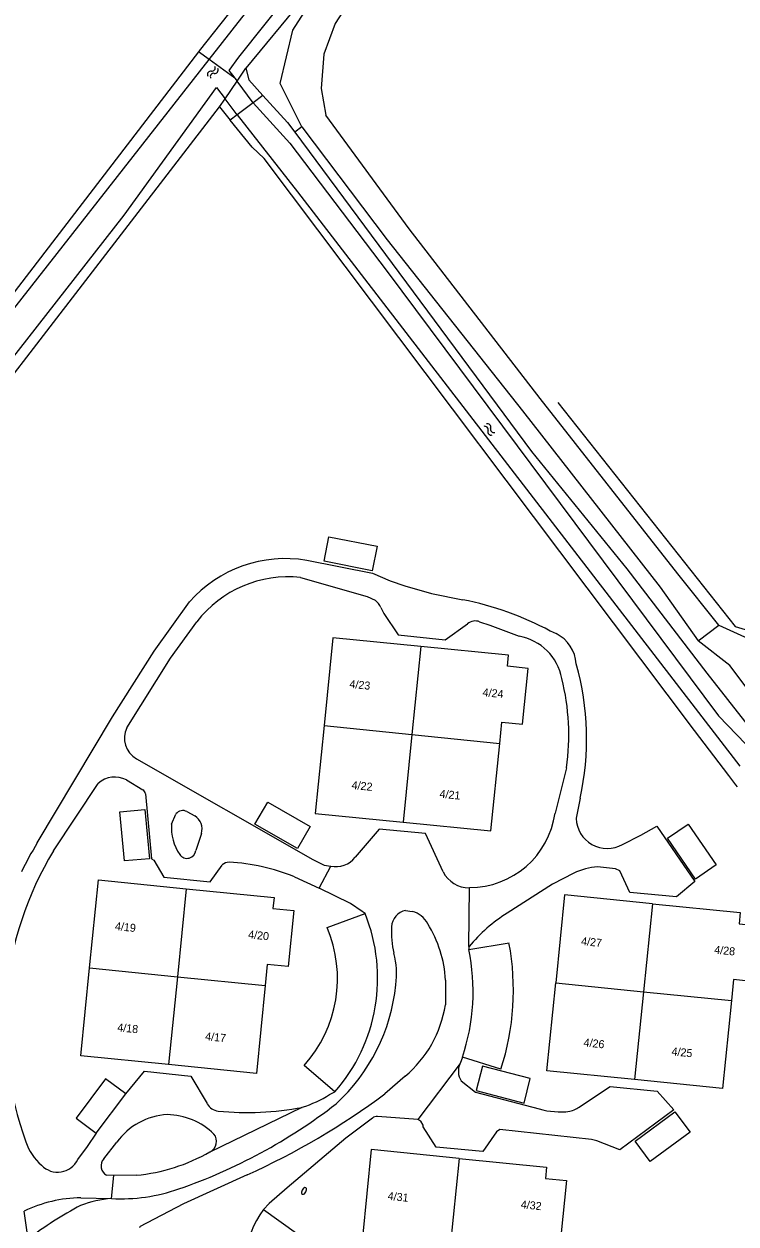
# Model space of a CAD drawing. Extents: x 136000 to 141014, y 402000 to 403500.
# Drawn here: x 137734.8 to 137823.8, y 402938.4 to 403088.3 of the extents above; entities that cross this region are included whole.
import ezdxf

# ---------------------------------------------------------------- set-up
doc = ezdxf.new("R2010")
doc.units = 0
for name, color, linetype in [('gg-afsc-hekwerk', 7, 'Continuous'), ('gg-anno-huisnummerreeks BGT', 7, 'Continuous'), ('gg-bbg-gedigitaliseerde bijgebouw', 7, 'Continuous'), ('gg-bbg-hoofdgebouw', 7, 'Continuous'), ('gg-bbg-tussenscheiding', 7, 'Continuous'), ('gg-knt-onverhard', 7, 'Continuous'), ('gg-knt-verharding', 7, 'Continuous'), ('gg-knt-verharding nz', 7, 'Continuous'), ('gg-kntw-bovenkant insteek waterloop', 7, 'Continuous'), ('gg-kntw-waterlijn', 7, 'Continuous'), ('gg-kwrk-lijn stuw', 7, 'Continuous'), ('gt-grn-groengrens', 7, 'Continuous'), ('gt-grn-vlakafsluiter', 7, 'Continuous'), ('gt-symb-brandkraan', 7, 'Continuous'), ('gt-symb-watersymbool', 7, 'Continuous')]:
    doc.layers.add(name, color=color, linetype=linetype)

# ---------------------------------------------------------------- blocks, each defined once
blk = doc.blocks.new('gt0-WA')
at = {"layer": 'gt-symb-watersymbool'}
for centre, start, end in [((-0.32, 0.02), 28.0725, 151.9275), ((0.43, 0.42), 208.0725, 331.9275), ((-0.32, -0.43), 28.0725, 151.9275), ((0.43, -0.03), 208.0725, 331.9275)]:
    blk.add_arc(centre, 0.425, start, end, dxfattribs=at)
blk = doc.blocks.new('gt0-BR')
at = {"layer": 'gt-symb-brandkraan'}
for centre, radius, start, end in [((-0.24, 0), 0.206, 107.5669, 252.4331), ((0.6, -2.66), 3, 106.892, 107.5669), ((0, -0.69), 0.938, 73.108, 106.892), ((-0.6, -2.66), 3, 72.4331, 73.108), ((0.24, 0), 0.206, 287.567, 72.4331), ((0.6, 2.66), 3, 252.4331, 253.108), ((0, 0.69), 0.938, 253.108, 286.8921), ((-0.6, 2.66), 3, 286.8921, 287.567)]:
    blk.add_arc(centre, radius, start, end, dxfattribs=at)

msp = doc.modelspace()

# ---------------------------------------------------------------- linework, layer by layer
at = {"layer": 'gg-afsc-hekwerk'}
msp.add_lwpolyline([(137801.52, 403040.96), (137823.69, 403012.99), (137826.49, 403012.14), (137826.96, 403011.96)], dxfattribs=at)
at = {"layer": 'gg-bbg-gedigitaliseerde bijgebouw'}
for p, q in [((137743.85, 402949.69), (137747.54, 402954.62)), ((137741.33, 402951.57), (137743.85, 402949.69))]:
    msp.add_line(p, q, dxfattribs=at)
for points in [[(137772.32, 403021.14), (137772.93, 403024.2), (137778.93, 403023.01), (137778.33, 403019.94), (137772.32, 403021.14)], [(137763.68, 402988.32), (137765.3, 402991.03), (137770.57, 402988), (137769.01, 402985.27), (137763.68, 402988.32)], [(137746.79, 402989.83), (137749.93, 402990.12), (137750.5, 402983.99), (137747.36, 402983.7), (137746.79, 402989.83)], [(137815.25, 402986.54), (137817.83, 402988.31), (137821.33, 402983.21), (137818.75, 402981.44), (137815.25, 402986.54)], [(137797.31, 402953.46), (137798.08, 402956.53), (137792.12, 402958.09), (137791.34, 402955.05), (137797.31, 402953.46)], [(137747.54, 402954.62), (137745.02, 402956.51), (137741.33, 402951.57)], [(137813.07, 402946.18), (137811.21, 402948.71), (137816.15, 402952.37), (137818.06, 402949.84), (137813.07, 402946.18)]]:
    msp.add_lwpolyline(points, dxfattribs=at)
at = {"layer": 'gg-bbg-hoofdgebouw'}
for points in [[(137784.4, 403010.49), (137773.43, 403011.58), (137772.31, 403000.61)], [(137794.26, 402998.39), (137794.53, 403001.04), (137797.12, 403000.78), (137797.82, 403007.76), (137795.23, 403008.02), (137795.36, 403009.41), (137784.4, 403010.49)], [(137772.31, 403000.61), (137771.19, 402989.64), (137782.18, 402988.55)], [(137782.18, 402988.55), (137793.17, 402987.46), (137794.26, 402998.39)], [(137743.02, 402970.36), (137744.13, 402981.33), (137755.1, 402980.24)], [(137755.1, 402980.24), (137766.07, 402979.15), (137765.93, 402977.76), (137768.53, 402977.5), (137767.82, 402970.52), (137765.22, 402970.78), (137764.96, 402968.14)], [(137813.34, 402978.35), (137802.37, 402979.46), (137801.27, 402968.48)], [(137813.34, 402978.35), (137824.31, 402977.25), (137824.17, 402975.86), (137826.77, 402975.61), (137826.07, 402968.62), (137823.47, 402968.88), (137823.21, 402966.26)], [(137752.88, 402958.27), (137741.91, 402959.38), (137743.02, 402970.36)], [(137764.96, 402968.14), (137763.85, 402957.16), (137752.88, 402958.27)], [(137811.12, 402956.39), (137800.16, 402957.49), (137801.27, 402968.48)], [(137823.21, 402966.26), (137822.11, 402955.28), (137811.12, 402956.39)], [(137789.18, 402946.55), (137778.22, 402947.65), (137777.1, 402936.66)], [(137789.18, 402946.55), (137800.13, 402945.44), (137800, 402944.05), (137802.59, 402943.8), (137801.9, 402936.82), (137799.31, 402937.07), (137799.05, 402934.44)]]:
    msp.add_lwpolyline(points, dxfattribs=at)
at = {"layer": 'gg-bbg-tussenscheiding'}
for p, q in [((137784.4, 403010.49), (137783.28, 402999.5)), ((137772.31, 403000.61), (137783.28, 402999.5)), ((137783.28, 402999.5), (137782.18, 402988.55)), ((137783.28, 402999.5), (137794.26, 402998.39)), ((137755.1, 402980.24), (137753.99, 402969.25)), ((137813.34, 402978.35), (137812.23, 402967.37)), ((137743.02, 402970.36), (137753.99, 402969.25)), ((137753.99, 402969.25), (137752.88, 402958.27)), ((137753.99, 402969.25), (137764.96, 402968.14)), ((137801.27, 402968.48), (137812.23, 402967.37)), ((137812.23, 402967.37), (137811.12, 402956.39)), ((137812.23, 402967.37), (137823.21, 402966.26)), ((137789.18, 402946.55), (137788.07, 402935.55))]:
    msp.add_line(p, q, dxfattribs=at)
at = {"layer": 'gg-knt-onverhard'}
for points in [[(137769.55, 403075.4), (137766.81, 403080.81), (137768.42, 403087.5), (137774.63, 403097.17), (137871.84, 403222.79)], [(137878.86, 403220.54), (137874.39, 403219.53), (137869.43, 403214.21), (137825.7, 403158.07), (137779.86, 403097.85), (137773.69, 403088.3), (137772.27, 403084.47), (137771.97, 403080.2), (137772.54, 403076.85)], [(137821.63, 403013.16), (137816.54, 403019.57), (137799.31, 403041.48), (137782.95, 403062.65), (137772.54, 403076.85)], [(137769.55, 403075.4), (137780.2, 403061.27), (137797.11, 403039.92), (137814.32, 403017.9), (137819.08, 403011.19)]]:
    msp.add_lwpolyline(points, dxfattribs=at)
at = {"layer": 'gg-knt-verharding'}
for p, q in [((137819.08, 403011.19), (137821.63, 403013.16)), ((137800.58, 403012.43), (137801.32, 403012.1)), ((137802.6, 402995.34), (137801.19, 402989.69)), ((137747.62, 402993.84), (137749.67, 402992.58)), ((137738.5, 402984.95), (137744.09, 402993.39)), ((137804.31, 402991.54), (137803.81, 402989.03)), ((137753.24, 402988.32), (137753.8, 402989.57)), ((137755.18, 402989.87), (137756.18, 402989.34)), ((137756.99, 402987.15), (137756.27, 402985.03)), ((137768.61, 402981.74), (137771.72, 402980.29)), ((137772.7, 402975.39), (137777.45, 402977.13)), ((137782.51, 402977.52), (137783.34, 402977.4)), ((137790.4, 402972.66), (137795.43, 402973.46)), ((137790.42, 402973.02), (137790.4, 402972.66)), ((137787.49, 402968.82), (137787.47, 402965.72)), ((137789.6, 402959.2), (137789.32, 402958.39)), ((137794.41, 402957.69), (137789.6, 402959.2)), ((137773.68, 402954.87), (137769.81, 402958.16)), ((137782.43, 402956.82), (137779.92, 402954.61)), ((137773.01, 402954.53), (137773.68, 402954.87)), ((137784.03, 402951.41), (137779.01, 402951.8)), ((137744.78, 402946.51), (137746.4, 402948.58)), ((137746.06, 402944.4), (137745.14, 402944.45)), ((137748.84, 402944.46), (137746.06, 402944.4)), ((137741.91, 402941.63), (137745.76, 402941.54)), ((137734.81, 402939.95), (137735.31, 402936.47)), ((137764.75, 402940.18), (137768.89, 402937.2))]:
    msp.add_line(p, q, dxfattribs=at)
for points in [[(137770.14, 403021.26), (137778.35, 403019.67), (137780.58, 403018.71), (137782.39, 403018.08), (137785.75, 403017.12), (137789.66, 403016.34)], [(137769.37, 403019.11), (137777.71, 403016.75), (137778.71, 403016.28)], [(137736.47, 402985.96), (137745.88, 403001.7), (137751.07, 403009.92), (137755.48, 403016.08)], [(137779.4, 403015.37), (137779.77, 403014.63), (137781.57, 403011.94), (137787.43, 403011.34), (137790.25, 403013.32)], [(137747.66, 403000.32), (137753.13, 403009.04), (137756.41, 403013.58)], [(137791.75, 403013.58), (137793.01, 403013.15), (137796.68, 403011.78)], [(137821.63, 403013.16), (137825.3, 403011.49), (137826.13, 403010.6)], [(137894.08, 402913.47), (137823.01, 403008.12), (137819.08, 403011.19)], [(137748.87, 402996.47), (137770.9, 402983.87), (137772.33, 402983.2), (137773.14, 402983.07)], [(137749.98, 402992.1), (137750.75, 402983.99), (137751.05, 402983.8), (137752.29, 402981.67), (137758.09, 402981.08), (137759.6, 402983.2)], [(137787.18, 402982.34), (137784.99, 402987.12), (137779.18, 402987.67), (137776.2, 402984.19)], [(137809.61, 402985.75), (137811.9, 402986.91), (137813.88, 402988.07), (137818.64, 402981.12), (137816.35, 402979.21), (137810.53, 402979.78), (137809.29, 402982.48), (137808.72, 402982.74), (137806.5, 402982.96)], [(137803.52, 402982.19), (137800.85, 402980.8), (137795.2, 402977.2)], [(137777.45, 402977.13), (137777.06, 402977.39), (137775.62, 402978.4), (137771.72, 402980.29)], [(137747.54, 402954.62), (137749.86, 402957.43), (137755.68, 402956.84), (137757.69, 402953.39)], [(137789.44, 402956.25), (137791.25, 402954.81), (137799.2, 402952.74)], [(137804.36, 402953.08), (137808.07, 402955.52), (137813.94, 402954.96), (137816.04, 402952.6), (137809.27, 402947.62), (137806.4, 402948.73), (137805.75, 402948.92), (137794.28, 402950.16), (137793.86, 402949.87), (137792.17, 402947.4), (137786.34, 402947.95), (137784.68, 402950.49), (137784.7, 402950.69), (137784.41, 402951.19), (137784.03, 402951.41)], [(137778.37, 402951.59), (137775.04, 402949.08), (137767.7, 402942.88), (137765.44, 402940.91), (137764.75, 402940.18)], [(137743.85, 402949.69), (137742.73, 402948.02), (137741.52, 402946.41)], [(137762.7, 402944.49), (137754.73, 402940.86), (137749.25, 402938.02), (137749.3, 402937.91)]]:
    msp.add_lwpolyline(points, dxfattribs=at)
for centre, radius, start, end in [((137767.49, 403005.43), 16.04, 80.4864, 138.4464), ((137767.8, 403004.86), 14.34, 83.6962, 142.5493), ((137777.25, 403014.44), 2.34, 23.2533, 51.6041), ((137782.36, 402978.71), 38.32, 61.613, 79.0242), ((137791.23, 403012.17), 1.51, 69.6238, 130.2657), ((137795.57, 403005.31), 6.56, 10.2799, 80.2799), ((137799.3, 403008.03), 4.54, 3.6424, 63.6678), ((137771.01, 402999), 34.12, 347.3717, 15.851), ((137774.42, 402999.47), 28.48, 351.6761, 14.2555), ((137750.28, 402999.03), 2.91, 153.6829, 241.1913), ((137746.18, 402991.1), 3.09, 62.1575, 132.3959), ((137749.28, 402991.99), 0.717, 9.0986, 56.2879), ((137754.66, 402988.93), 1.07, 60.7123, 143.1821), ((137755.06, 402987.67), 2.01, 344.9578, 56.1198), ((137790.46, 402991.2), 10.83, 270.0897, 351.9846), ((137807.72, 402989.17), 3.91, 182.11, 298.9226), ((137759.41, 402987.94), 6.18, 176.5287, 213.8214), ((137774.2, 402963.25), 41.78, 148.7014, 200.4781), ((137774.66, 402962.79), 44.67, 148.7562, 154.0539), ((137755.18, 402985.13), 1.1, 214.7752, 354.8193), ((137760.45, 402982.31), 1.24, 89.9247, 133.8391), ((137759.08, 402958.05), 25.53, 68.0878, 86.9097), ((137773.81, 402985.97), 2.98, 257.0919, 323.1664), ((137790.45, 402984.06), 3.7, 207.8639, 270.3571), ((137806.95, 402975.08), 7.89, 93.2657, 115.7378), ((137757.45, 402969.07), 21.56, 318.8124, 21.9483), ((137782.96, 402975.35), 2.22, 101.7728, 176.3812), ((137782.55, 402974.43), 3.07, 27.8452, 75.1618), ((137806.93, 402958.98), 21.67, 122.7591, 139.6009), ((137772.46, 402967.95), 15.06, 3.3221, 31.7181), ((137757.73, 402969.04), 16.26, 317.9882, 22.9717), ((137792.4, 402974.79), 11.67, 176.5502, 192.937), ((137765.34, 402967.39), 25.6, 341.3321, 11.8761), ((137764.41, 402967.54), 31.57, 341.8172, 10.8035), ((137771.46, 402969.59), 9.91, 352.1758, 15.1453), ((137758.02, 402970.6), 23.38, 312.4842, 354.1917), ((137773.15, 402967.96), 14.5, 309.8266, 351.116), ((137791.19, 402957.42), 2.1, 152.7488, 213.8487), ((137723.5, 403030.82), 94.82, 294.4239, 306.5136), ((137764.77, 402967.74), 15.57, 288.0359, 301.9576), ((137731.79, 403007.55), 68.57, 289.0389, 307.7915), ((137759.27, 402954.25), 1.8, 208.8285, 264.0582), ((137802.18, 402955.91), 3.57, 283.6459, 307.5075), ((137753.18, 402943.66), 8.37, 93.2053, 144.0601), ((137752.57, 402943.42), 8.6, 45.9098, 89.0679), ((137762.69, 402989.3), 37.02, 264.4157, 280.7504), ((137778.95, 402950.86), 0.936, 86.5, 128.8149), ((137801.85, 402962.06), 9.7, 254.136, 276.9544), ((137741.05, 402950.5), 6.28, 197.3092, 229.8723), ((137757.4, 402948.69), 1.47, 296.7477, 38.0688), ((137746.87, 402966.68), 22.31, 275.0577, 300.088), ((137739.02, 402947.61), 2.78, 223.5938, 334.2511), ((137745.78, 402945.62), 1.34, 138.5976, 241.2022), ((137746.92, 402963.57), 22.06, 266.9807, 289.165), ((137742.18, 402924.68), 16.96, 90.897, 115.7352), ((137747.22, 402925.72), 15.89, 95.301, 109.6027), ((137766.16, 402895.56), 51.24, 118.272, 127.0277), ((137773.28, 402933.62), 10.76, 142.4826, 210.5363)]:
    msp.add_arc(centre, radius, start, end, dxfattribs=at)
at = {"layer": 'gg-knt-verharding nz'}
for p, q in [((137771.72, 402980.29), (137773.14, 402983.07)), ((137790.42, 402973.02), (137790.48, 402980.37)), ((137789.32, 402958.39), (137784.03, 402951.41)), ((137758.06, 402947.38), (137769.59, 402952.94)), ((137745.76, 402941.54), (137746.06, 402944.4))]:
    msp.add_line(p, q, dxfattribs=at)
at = {"layer": 'gg-kntw-bovenkant insteek waterloop'}
for p, q in [((137764.68, 403079.31), (137767.76, 403075.96)), ((137759.26, 403077.91), (137760.6, 403076.25)), ((137767.76, 403075.96), (137768.67, 403074.73)), ((137818.59, 403000), (137764.83, 403071.47)), ((137822.88, 402994.39), (137818.59, 403000))]:
    msp.add_line(p, q, dxfattribs=at)
for points in [[(137794.71, 403124.02), (137788.62, 403116.1), (137769.5, 403091.15), (137762.53, 403082.72)], [(137756.64, 403084.79), (137756.73, 403084.91), (137764.85, 403095.2)], [(137756.64, 403084.79), (137720.91, 403038.29), (137679.58, 402985.37), (137669.69, 402970.91)], [(137762.53, 403082.72), (137762.93, 403081.26), (137764.68, 403079.31)], [(137674.82, 402967.13), (137709.51, 403013.35), (137759.26, 403077.91)], [(137764.83, 403071.47), (137763.33, 403072.86), (137760.6, 403076.25)], [(137768.67, 403074.73), (137798.24, 403034.83), (137810.17, 403020.19), (137820.15, 403007.16), (137828.35, 402996.71)], [(137823.96, 402992.98), (137823.78, 402993.21), (137822.88, 402994.39)]]:
    msp.add_lwpolyline(points, dxfattribs=at)
at = {"layer": 'gg-kntw-waterlijn'}
for p, q in [((137761.16, 403081.47), (137761.44, 403081.1)), ((137763.47, 403078.4), (137761.44, 403081.1)), ((137761.47, 403076.91), (137759.94, 403078.91))]:
    msp.add_line(p, q, dxfattribs=at)
for points in [[(137757.95, 403083.83), (137785.51, 403118.96), (137835.56, 403184.14)], [(137837.86, 403182.36), (137834.77, 403178.2), (137816.8, 403154.9), (137785, 403113.41), (137761.62, 403084.09), (137760.43, 403082.45), (137761.16, 403081.47)], [(137671.14, 402969.84), (137676.94, 402978.47), (137687.25, 402992.98), (137731.38, 403049.95), (137757.95, 403083.83)], [(137673.43, 402968.16), (137691.79, 402993.34), (137747.33, 403064.39), (137758.88, 403080.31), (137759.94, 403078.91)], [(137763.47, 403078.4), (137768.03, 403073.38), (137780.19, 403057.34), (137821.62, 403001.84), (137825.03, 402998.28), (137825.52, 402998.06), (137826, 402997.89), (137826.56, 402997.88), (137827.19, 402997.84), (137827.34, 402997.72), (137827.27, 402997.38), (137826.85, 402996.82), (137826.45, 402996.24), (137826.67, 402995.67), (137826.77, 402995.43), (137826.79, 402995.4)], [(137761.47, 403076.91), (137769.01, 403067.3), (137824.27, 402995.55)]]:
    msp.add_lwpolyline(points, dxfattribs=at)
at = {"layer": 'gg-kwrk-lijn stuw'}
for p, q in [((137764.68, 403079.31), (137763.47, 403078.4)), ((137763.47, 403078.4), (137761.47, 403076.91)), ((137761.47, 403076.91), (137760.6, 403076.25))]:
    msp.add_line(p, q, dxfattribs=at)
at = {"layer": 'gt-grn-groengrens'}
msp.add_line((137769.55, 403075.4), (137768.67, 403074.73), dxfattribs=at)
at = {"layer": 'gt-grn-vlakafsluiter'}
for p, q in [((137757.95, 403083.83), (137756.64, 403084.79)), ((137761.16, 403081.47), (137757.95, 403083.83)), ((137761.44, 403081.1), (137762.53, 403082.72)), ((137759.94, 403078.91), (137761.44, 403081.1)), ((137759.26, 403077.91), (137759.94, 403078.91))]:
    msp.add_line(p, q, dxfattribs=at)

# ---------------------------------------------------------------- block references
at = {"layer": 'gt-symb-brandkraan', "rotation": 62.09224023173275}
msp.add_blockref('gt0-BR', (137769.81, 402942.48), dxfattribs=at)
at = {"layer": 'gt-symb-watersymbool'}
for p, rotation in [((137758.37, 403082.18), 53.290465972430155), ((137792.93, 403037.65), -45.64829798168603)]:
    msp.add_blockref('gt0-WA', p, dxfattribs=dict(at, rotation=rotation))

# ---------------------------------------------------------------- texts
at = {"layer": 'gg-anno-huisnummerreeks BGT'}
for s, rotation, p in [('4/23', 354.2, (137775.45, 403005.34)), ('4/24', 354.3, (137792.09, 403004.3)), ('4/22', 354.3, (137775.72, 402992.71)), ('4/21', 354.3, (137786.71, 402991.62)), ('4/19', 354.3, (137746.15, 402975.08)), ('4/20', 354.2, (137762.79, 402974.05)), ('4/27', 354.3, (137804.4, 402973.21)), ('4/28', 354.3, (137821.04, 402972.15)), ('4/18', 354.2, (137746.44, 402962.44)), ('4/17', 354.2, (137757.42, 402961.33)), ('4/26', 354.3, (137804.71, 402960.55)), ('4/25', 354.3, (137815.7, 402959.44)), ('4/31', 354.1, (137780.23, 402941.39)), ('4/32', 354.4, (137796.86, 402940.33))]:
    msp.add_text(s, height=1, rotation=rotation, dxfattribs=at).set_placement(p)

doc.saveas('drawing.dxf')
